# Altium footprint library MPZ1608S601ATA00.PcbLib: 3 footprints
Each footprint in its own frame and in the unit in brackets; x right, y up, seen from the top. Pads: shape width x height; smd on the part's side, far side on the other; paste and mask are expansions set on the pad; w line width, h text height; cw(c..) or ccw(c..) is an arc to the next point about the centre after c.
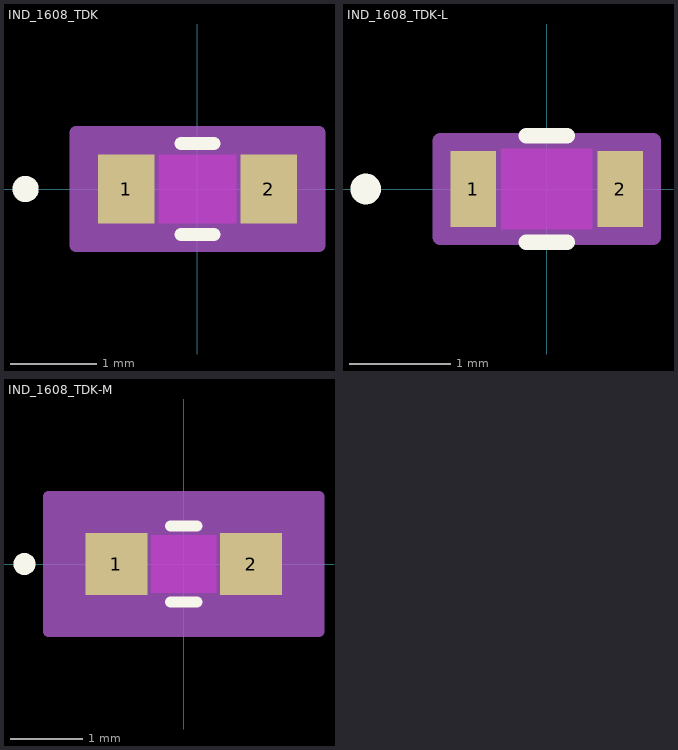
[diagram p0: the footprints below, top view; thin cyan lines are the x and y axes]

## IND_1608_TDK [mm]
pads (2):
  rect 0.656x0.8 smd paste+0 mask+0: 1(-0.828,0) 2(0.828,0)
Top Layer keep-out:
  region: -0.449,-0.349 -0.449,0.349 0.449,0.349 0.449,-0.349
Top Overlay:
  circle w0.152: c-1.994,0 r0.076
  lines w0.152: -0.192,-0.527 0.192,-0.527 ; -0.192,0.527 0.192,0.527
  text ".Designator" at -3.492,-0.635 h1.27
Keep-Out Layer:
  region: -0.449,-0.4 -0.449,0.4 0.449,0.4 0.449,-0.4
Mechanical 13:
  circle w0.025: c-0.701,0 r0.076
  lines w0.025: -0.8,-0.4 -0.8,0.4 ; -0.8,-0.4 -0.5,-0.4 -0.5,0.4 -0.8,0.4 ; -0.8,-0.4 0.8,-0.4 ; -0.8,-0.4 -0.8,0.4 ; -0.8,0.4 0.8,0.4 ; 0.8,-0.4 0.5,-0.4 0.5,0.4 0.8,0.4 ; 0.8,-0.4 0.8,0.4 ; 0.8,-0.4 0.8,0.4
  text ".Designator" at -3.492,-0.635 h1.27
Mechanical 15:
  region: 1.41,-0.654 -1.41,-0.654 -1.41,0.654 1.41,0.654
  lines w0.152: -1.41,-0.654 -1.41,0.654 1.41,0.654 1.41,-0.654 -1.41,-0.654
3D body "IND_1608_TDK.step": height 0.8, standoff 0, extent -0.8,-0.4 0.8,0.4

## IND_1608_TDK-L [mm]
pads (2):
  rect 0.452x0.749 smd paste+0 mask+0: 1(-0.726,0) 2(0.726,0)
Top Layer keep-out:
  region: -0.449,-0.349 -0.449,0.349 0.449,0.349 0.449,-0.349
Top Overlay:
  circle w0.152: c-1.791,0 r0.076
  lines w0.152: -0.204,-0.527 0.204,-0.527 ; -0.204,0.527 0.204,0.527
  text ".Designator" at -3.492,-0.635 h1.27
Keep-Out Layer:
  region: -0.449,-0.4 -0.449,0.4 0.449,0.4 0.449,-0.4
Mechanical 13:
  circle w0.025: c-0.599,0 r0.076
  lines w0.025: -0.8,-0.4 -0.8,0.4 ; -0.8,-0.4 -0.5,-0.4 -0.5,0.4 -0.8,0.4 ; -0.8,-0.4 0.8,-0.4 ; -0.8,-0.4 -0.8,0.4 ; -0.8,0.4 0.8,0.4 ; 0.8,-0.4 0.5,-0.4 0.5,0.4 0.8,0.4 ; 0.8,-0.4 0.8,0.4 ; 0.8,-0.4 0.8,0.4
  text ".Designator" at -3.492,-0.635 h1.27
Mechanical 15:
  region: 1.054,-0.476 -1.054,-0.476 -1.054,0.476 1.054,0.476
  lines w0.152: -1.054,-0.476 -1.054,0.476 1.054,0.476 1.054,-0.476 -1.054,-0.476
3D body "IND_1608_TDK.step": height 0.8, standoff 0, extent -0.8,-0.4 0.8,0.4

## IND_1608_TDK-M [mm]
pads (2):
  rect 0.859x0.851 smd paste+0 mask+0: 1(-0.929,0) 2(0.929,0)
Top Layer keep-out:
  region: -0.449,-0.349 -0.449,0.349 0.449,0.349 0.449,-0.349
Top Overlay:
  circle w0.152: c-2.197,0 r0.076
  lines w0.152: -0.183,-0.527 0.183,-0.527 ; -0.183,0.527 0.183,0.527
  text ".Designator" at -3.492,-0.635 h1.27
Keep-Out Layer:
  region: -0.449,-0.4 -0.449,0.4 0.449,0.4 0.449,-0.4
Mechanical 13:
  circle w0.025: c-0.802,0 r0.076
  lines w0.025: -0.8,-0.4 -0.8,0.4 ; -0.8,-0.4 -0.5,-0.4 -0.5,0.4 -0.8,0.4 ; -0.8,-0.4 0.8,-0.4 ; -0.8,-0.4 -0.8,0.4 ; -0.8,0.4 0.8,0.4 ; 0.8,-0.4 0.5,-0.4 0.5,0.4 0.8,0.4 ; 0.8,-0.4 0.8,0.4 ; 0.8,-0.4 0.8,0.4
  text ".Designator" at -3.492,-0.635 h1.27
Mechanical 15:
  region: 1.867,-0.933 -1.867,-0.933 -1.867,0.933 1.867,0.933
  lines w0.152: -1.867,-0.933 -1.867,0.933 1.867,0.933 1.867,-0.933 -1.867,-0.933
3D body "IND_1608_TDK.step": height 0.8, standoff 0, extent -0.8,-0.4 0.8,0.4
